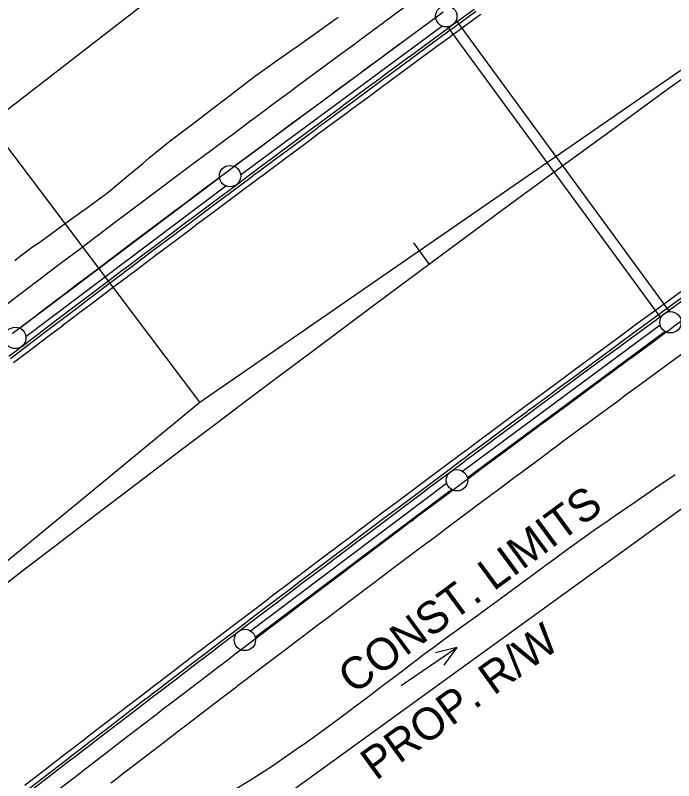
# Model space of a CAD drawing. Extents: x 1147550 to 1149124, y 2017436 to 2018779.
# Drawn here: x 1147976.6 to 1148099.8, y 2017760.9 to 2017904.1 of the extents above; entities that cross this region are included whole.
import ezdxf

# ---------------------------------------------------------------- set-up
doc = ezdxf.new("R2010")
doc.units = 0
for name, color, linetype in [('S_EDGE_CONCRETE', 7, 'Continuous'), ('S_MAILBOX', 7, 'Continuous'), ('S_RDW_PT_SYM', 7, 'Continuous'), ('S_SECONDARY_CTL', 7, 'Continuous'), ('S_TANK', 7, 'Continuous'), ('S_TELEPHONE_UTILITIES', 7, 'Continuous'), ('S_TELEPHONE_UTILITIES_ANNOT', 7, 'Continuous')]:
    doc.layers.add(name, color=color, linetype=linetype)

msp = doc.modelspace()

# ---------------------------------------------------------------- linework, layer by layer
at = {"layer": 'S_EDGE_CONCRETE'}
for p, q in [((1148011.14, 2017831.73), (1148208.89, 2017968.31)), ((1147825.51, 2017679.08), (1148011.14, 2017831.73))]:
    msp.add_line(p, q, dxfattribs=at)
msp.add_lwpolyline([(1148051.07, 2017861.54), (1148054.05, 2017857.52)], dxfattribs=at)
msp.add_arc((1151464.82, 2013253.76), 5729.58, 124.62946, 129.43332, dxfattribs=at)
at = {"layer": 'S_MAILBOX'}
for points in [[(1147550.1, 2017525.89), (1147894.72, 2017801.4), (1147903.55, 2017831.14), (1148035.64, 2017933.4), (1148261.5, 2018084.85), (1148285.74, 2018084.65), (1148479.1, 2018223.18), (1148835.76, 2018573.62)], [(1147623.68, 2017436.42), (1147751.67, 2017548.43), (1147958.55, 2017704.02), (1148020.45, 2017753.36), (1148124.6, 2017828.73), (1148174.25, 2017853.51), (1148282.74, 2017941.53), (1148421.63, 2018031.39), (1148612.18, 2018197.22), (1148639.91, 2018214.06), (1148753.45, 2018306.48), (1148799.03, 2018350.69)]]:
    msp.add_lwpolyline(points, dxfattribs=at)
at = {"layer": 'S_RDW_PT_SYM'}
msp.add_lwpolyline([(1148011.14, 2017831.73), (1147938.86, 2017927.53)], dxfattribs=at)
at = {"layer": 'S_SECONDARY_CTL'}
for points in [[(1147976.51, 2017858.28), (1147977.59, 2017859.11), (1147979.56, 2017860.62), (1147981.65, 2017862.09), (1147985.74, 2017865.05), (1147988.57, 2017867.1), (1147988.68, 2017867.18), (1147989.82, 2017868.01), (1147992.23, 2017869.76), (1147993.88, 2017870.99), (1147997.77, 2017874.22), (1148000.42, 2017876.43), (1148000.58, 2017876.56), (1148001.64, 2017877.45), (1148004.32, 2017879.68), (1148005.54, 2017880.65), (1148009.58, 2017883.66), (1148012.26, 2017885.71), (1148012.55, 2017885.93), (1148013.59, 2017886.73), (1148016.75, 2017889.15), (1148017.6, 2017889.79), (1148021.6, 2017892.85), (1148024.32, 2017894.82), (1148024.62, 2017895.03), (1148025.7, 2017895.79), (1148029.36, 2017898.37), (1148029.82, 2017898.7), (1148033.94, 2017901.6), (1148036.65, 2017903.51), (1148036.99, 2017903.76)], [(1148017.72, 2017759.31), (1148020.73, 2017761.13), (1148024.9, 2017763.83), (1148027.72, 2017765.8), (1148027.85, 2017765.89), (1148028.96, 2017766.67), (1148030.56, 2017767.78), (1148033.02, 2017769.5), (1148037, 2017772.45), (1148039.72, 2017774.48), (1148039.89, 2017774.61), (1148040.96, 2017775.42), (1148042.9, 2017776.89), (1148044.91, 2017778.4), (1148048.87, 2017781.37), (1148051.6, 2017783.45), (1148051.7, 2017783.54), (1148052.8, 2017784.38), (1148055.16, 2017786.11), (1148056.79, 2017787.31), (1148060.79, 2017790.22), (1148063.54, 2017792.22), (1148063.7, 2017792.33), (1148064.81, 2017793.11), (1148067.56, 2017795.14), (1148068.79, 2017796.05), (1148072.78, 2017798.99), (1148075.44, 2017800.95), (1148075.73, 2017801.16), (1148076.77, 2017801.92), (1148079.92, 2017804.23), (1148080.76, 2017804.84), (1148084.77, 2017807.74), (1148087.49, 2017809.61), (1148087.78, 2017809.81), (1148088.85, 2017810.55), (1148092.48, 2017813.04), (1148092.93, 2017813.35), (1148097.02, 2017816.15), (1148099.71, 2017817.98), (1148100.05, 2017818.23)]]:
    msp.add_lwpolyline(points, dxfattribs=at)
at = {"layer": 'S_TANK'}
for p, q in [((1148048.8, 2017778.76), (1148059.18, 2017785.86)), ((1148059.18, 2017785.86), (1148055.21, 2017784.84)), ((1148059.18, 2017785.86), (1148056.79, 2017782.53))]:
    msp.add_line(p, q, dxfattribs=at)
at = {"layer": 'S_TELEPHONE_UTILITIES'}
for points in [[(1147972.95, 2017848.55), (1147976.96, 2017851.6), (1147979.72, 2017853.69), (1147979.89, 2017853.82), (1147980.97, 2017854.64), (1147982.95, 2017856.14), (1147984.99, 2017857.68), (1147989.01, 2017860.71), (1147991.8, 2017862.82), (1147991.91, 2017862.9), (1147993.03, 2017863.75), (1147995.41, 2017865.54), (1147997.05, 2017866.77), (1148001.08, 2017869.8), (1148003.84, 2017871.87), (1148004, 2017871.99), (1148005.11, 2017872.82), (1148007.9, 2017874.9), (1148009.14, 2017875.84), (1148013.18, 2017878.85), (1148015.87, 2017880.86), (1148016.16, 2017881.08), (1148017.21, 2017881.86), (1148020.41, 2017884.24), (1148021.26, 2017884.87), (1148025.3, 2017887.87), (1148027.99, 2017889.87), (1148028.28, 2017890.08), (1148029.34, 2017890.87), (1148032.94, 2017893.53), (1148033.39, 2017893.87), (1148037.44, 2017896.86), (1148040.1, 2017898.82), (1148040.45, 2017899.07), (1148041.49, 2017899.85), (1148045.5, 2017902.8), (1148045.55, 2017902.83), (1148049.61, 2017905.82)], [(1147975.36, 2017840.34), (1147977.79, 2017842.18), (1147981.79, 2017845.22), (1147984.55, 2017847.31), (1147984.72, 2017847.44), (1147985.8, 2017848.26), (1147987.78, 2017849.76), (1147989.81, 2017851.3), (1147993.83, 2017854.33), (1147996.61, 2017856.43), (1147996.72, 2017856.51), (1147997.84, 2017857.35), (1148000.22, 2017859.14), (1148001.86, 2017860.38), (1148005.88, 2017863.4), (1148008.64, 2017865.47), (1148008.8, 2017865.59), (1148009.91, 2017866.42), (1148012.69, 2017868.5), (1148013.93, 2017869.43), (1148017.96, 2017872.44), (1148020.65, 2017874.45), (1148020.95, 2017874.66), (1148021.99, 2017875.44), (1148025.18, 2017877.82), (1148026.03, 2017878.45), (1148030.07, 2017881.45), (1148032.75, 2017883.44), (1148033.05, 2017883.66), (1148034.11, 2017884.44), (1148037.7, 2017887.1), (1148038.15, 2017887.43), (1148042.19, 2017890.42), (1148044.85, 2017892.38), (1148045.19, 2017892.64), (1148046.24, 2017893.41), (1148050.24, 2017896.35), (1148050.29, 2017896.39), (1148054.34, 2017899.37), (1148056.93, 2017901.27), (1148057.39, 2017901.6), (1148058.4, 2017902.34), (1148062.46, 2017905.31)], [(1147975.66, 2017839.94), (1147978.09, 2017841.79), (1147982.1, 2017844.83), (1147984.85, 2017846.91), (1147985.02, 2017847.04), (1147986.1, 2017847.86), (1147988.08, 2017849.36), (1147990.11, 2017850.9), (1147994.13, 2017853.93), (1147996.91, 2017856.03), (1147997.02, 2017856.11), (1147998.14, 2017856.96), (1148000.52, 2017858.74), (1148002.16, 2017859.98), (1148006.18, 2017863), (1148008.94, 2017865.07), (1148009.1, 2017865.19), (1148010.21, 2017866.02), (1148012.99, 2017868.1), (1148014.23, 2017869.03), (1148018.26, 2017872.04), (1148020.95, 2017874.04), (1148021.24, 2017874.26), (1148022.29, 2017875.04), (1148025.48, 2017877.42), (1148026.33, 2017878.05), (1148030.36, 2017881.04), (1148033.05, 2017883.04), (1148033.34, 2017883.26), (1148034.4, 2017884.04), (1148038, 2017886.7), (1148038.45, 2017887.03), (1148042.49, 2017890.02), (1148045.15, 2017891.98), (1148045.49, 2017892.23), (1148046.54, 2017893.01), (1148050.54, 2017895.95), (1148050.59, 2017895.99), (1148054.64, 2017898.96), (1148057.23, 2017900.86), (1148057.69, 2017901.2), (1148058.69, 2017901.94), (1148062.75, 2017904.91)], [(1147975.97, 2017844.57), (1147979.98, 2017847.61), (1147982.73, 2017849.7), (1147982.91, 2017849.83), (1147983.99, 2017850.65), (1147985.97, 2017852.15), (1147988, 2017853.69), (1147992.02, 2017856.72), (1147994.8, 2017858.82), (1147994.92, 2017858.91), (1147996.04, 2017859.75), (1147998.42, 2017861.54), (1148000.06, 2017862.78), (1148004.08, 2017865.8), (1148006.84, 2017867.87), (1148007, 2017867.99), (1148008.11, 2017868.82), (1148010.89, 2017870.9), (1148012.14, 2017871.83), (1148016.17, 2017874.84), (1148018.86, 2017876.85), (1148019.15, 2017877.07), (1148020.2, 2017877.85), (1148023.39, 2017880.22), (1148024.24, 2017880.85), (1148028.28, 2017883.86), (1148030.97, 2017885.85), (1148031.26, 2017886.07), (1148032.32, 2017886.85), (1148035.92, 2017889.51), (1148036.36, 2017889.85), (1148040.41, 2017892.84), (1148043.07, 2017894.8), (1148043.41, 2017895.05), (1148044.46, 2017895.82), (1148048.47, 2017898.77), (1148048.51, 2017898.81), (1148052.57, 2017901.79), (1148055.16, 2017903.69), (1148055.62, 2017904.02), (1148056.63, 2017904.76)], [(1147976.27, 2017839.14), (1147978.7, 2017840.99), (1147982.7, 2017844.03), (1147985.45, 2017846.12), (1147985.62, 2017846.25), (1147986.71, 2017847.07), (1147988.68, 2017848.56), (1147990.72, 2017850.1), (1147994.73, 2017853.13), (1147997.51, 2017855.23), (1147997.62, 2017855.31), (1147998.74, 2017856.16), (1148001.12, 2017857.94), (1148002.76, 2017859.18), (1148006.78, 2017862.2), (1148009.54, 2017864.27), (1148009.7, 2017864.39), (1148010.81, 2017865.21), (1148013.59, 2017867.3), (1148014.83, 2017868.23), (1148018.86, 2017871.24), (1148021.55, 2017873.24), (1148021.84, 2017873.46), (1148022.89, 2017874.24), (1148026.08, 2017876.61), (1148026.92, 2017877.24), (1148030.96, 2017880.24), (1148033.65, 2017882.24), (1148033.94, 2017882.45), (1148035, 2017883.24), (1148038.59, 2017885.9), (1148039.04, 2017886.23), (1148043.08, 2017889.22), (1148045.74, 2017891.18), (1148046.08, 2017891.43), (1148047.13, 2017892.2), (1148051.13, 2017895.15), (1148051.18, 2017895.18), (1148055.23, 2017898.16), (1148057.82, 2017900.06), (1148058.28, 2017900.39), (1148059.29, 2017901.13), (1148063.34, 2017904.1), (1148063.7, 2017904.36)], [(1147978.34, 2017760.07), (1147981.9, 2017762.82), (1147985.84, 2017765.86), (1147986.62, 2017766.46), (1147988.64, 2017768.02), (1147988.65, 2017768.02), (1147989.77, 2017768.89), (1147990.54, 2017769.48), (1147993.72, 2017771.92), (1147997.66, 2017774.95), (1148000.43, 2017777.07), (1148000.5, 2017777.12), (1148001.61, 2017777.97), (1148002.77, 2017778.86), (1148005.56, 2017780.99), (1148009.51, 2017784.01), (1148012.25, 2017786.1), (1148012.38, 2017786.2), (1148013.46, 2017787.02), (1148015.02, 2017788.21), (1148017.42, 2017790.03), (1148021.38, 2017793.04), (1148024.1, 2017795.1), (1148024.27, 2017795.23), (1148025.34, 2017796.04), (1148027.29, 2017797.52), (1148029.31, 2017799.04), (1148033.28, 2017802.04), (1148036.03, 2017804.11), (1148036.14, 2017804.2), (1148037.25, 2017805.03), (1148039.6, 2017806.8), (1148041.22, 2017808.02), (1148045.19, 2017811.01), (1148047.92, 2017813.05), (1148048.08, 2017813.17), (1148049.17, 2017813.99), (1148051.92, 2017816.05), (1148053.15, 2017816.97), (1148057.14, 2017819.95), (1148059.8, 2017821.93), (1148060.09, 2017822.14), (1148061.12, 2017822.92), (1148064.27, 2017825.26), (1148065.11, 2017825.89), (1148069.1, 2017828.85), (1148071.76, 2017830.82), (1148072.05, 2017831.04), (1148073.1, 2017831.81), (1148076.65, 2017834.44), (1148077.09, 2017834.77), (1148081.09, 2017837.72), (1148083.72, 2017839.66), (1148084.06, 2017839.91), (1148085.09, 2017840.68), (1148089.05, 2017843.59), (1148089.1, 2017843.62), (1148093.1, 2017846.57), (1148095.67, 2017848.45), (1148096.12, 2017848.78), (1148097.11, 2017849.51), (1148101.13, 2017852.45)], [(1147978.95, 2017759.28), (1147982.51, 2017762.03), (1147986.45, 2017765.06), (1147987.23, 2017765.67), (1147989.25, 2017767.22), (1147989.26, 2017767.23), (1147990.38, 2017768.1), (1147991.15, 2017768.69), (1147994.32, 2017771.13), (1147998.27, 2017774.16), (1148001.04, 2017776.28), (1148001.11, 2017776.33), (1148002.21, 2017777.18), (1148003.37, 2017778.07), (1148006.16, 2017780.2), (1148010.11, 2017783.22), (1148012.86, 2017785.31), (1148012.98, 2017785.4), (1148014.07, 2017786.23), (1148015.62, 2017787.41), (1148018.03, 2017789.24), (1148021.98, 2017792.24), (1148024.71, 2017794.31), (1148024.88, 2017794.44), (1148025.95, 2017795.25), (1148027.9, 2017796.72), (1148029.91, 2017798.25), (1148033.88, 2017801.24), (1148036.63, 2017803.32), (1148036.74, 2017803.4), (1148037.85, 2017804.23), (1148040.2, 2017806), (1148041.82, 2017807.22), (1148045.8, 2017810.21), (1148048.52, 2017812.25), (1148048.68, 2017812.37), (1148049.77, 2017813.19), (1148052.52, 2017815.25), (1148053.75, 2017816.17), (1148057.74, 2017819.14), (1148060.39, 2017821.13), (1148060.68, 2017821.34), (1148061.72, 2017822.12), (1148064.87, 2017824.46), (1148065.71, 2017825.08), (1148069.7, 2017828.05), (1148072.36, 2017830.02), (1148072.64, 2017830.23), (1148073.69, 2017831.01), (1148077.25, 2017833.64), (1148077.69, 2017833.97), (1148081.69, 2017836.92), (1148084.31, 2017838.86), (1148084.65, 2017839.11), (1148085.69, 2017839.87), (1148089.64, 2017842.78), (1148089.69, 2017842.82), (1148093.7, 2017845.76), (1148096.26, 2017847.64), (1148096.71, 2017847.97), (1148097.71, 2017848.7), (1148101.72, 2017851.64)], [(1147979.26, 2017758.88), (1147982.82, 2017761.63), (1147986.75, 2017764.67), (1147987.54, 2017765.28), (1147989.55, 2017766.83), (1147989.56, 2017766.83), (1147990.69, 2017767.7), (1147991.45, 2017768.29), (1147994.63, 2017770.73), (1147998.57, 2017773.76), (1148001.35, 2017775.88), (1148001.41, 2017775.93), (1148002.52, 2017776.78), (1148003.68, 2017777.67), (1148006.47, 2017779.8), (1148010.42, 2017782.82), (1148013.16, 2017784.91), (1148013.29, 2017785), (1148014.37, 2017785.83), (1148015.93, 2017787.01), (1148018.33, 2017788.84), (1148022.29, 2017791.85), (1148025.01, 2017793.91), (1148025.18, 2017794.04), (1148026.25, 2017794.85), (1148028.2, 2017796.32), (1148030.21, 2017797.85), (1148034.18, 2017800.84), (1148036.93, 2017802.92), (1148037.04, 2017803), (1148038.15, 2017803.83), (1148040.5, 2017805.6), (1148042.12, 2017806.82), (1148046.1, 2017809.81), (1148048.82, 2017811.85), (1148048.98, 2017811.97), (1148050.07, 2017812.79), (1148052.82, 2017814.85), (1148054.05, 2017815.77), (1148058.03, 2017818.74), (1148060.69, 2017820.73), (1148060.98, 2017820.94), (1148062.02, 2017821.71), (1148065.17, 2017824.06), (1148066.01, 2017824.68), (1148070, 2017827.65), (1148072.65, 2017829.62), (1148072.94, 2017829.83), (1148073.99, 2017830.61), (1148077.54, 2017833.24), (1148077.99, 2017833.56), (1148081.98, 2017836.52), (1148084.61, 2017838.46), (1148084.95, 2017838.71), (1148085.98, 2017839.47), (1148089.94, 2017842.38), (1148089.99, 2017842.42), (1148093.99, 2017845.36), (1148096.55, 2017847.24), (1148097.01, 2017847.57), (1148098, 2017848.3), (1148102.01, 2017851.23)], [(1147984.65, 2017759.26), (1147988.58, 2017762.29), (1147989.37, 2017762.9), (1147991.38, 2017764.45), (1147991.39, 2017764.46), (1147992.52, 2017765.32), (1147993.28, 2017765.91), (1147996.46, 2017768.35), (1148000.4, 2017771.38), (1148003.17, 2017773.5), (1148003.23, 2017773.55), (1148004.34, 2017774.4), (1148005.5, 2017775.29), (1148008.29, 2017777.42), (1148012.24, 2017780.43), (1148014.98, 2017782.52), (1148015.1, 2017782.62), (1148016.19, 2017783.44), (1148017.74, 2017784.63), (1148020.14, 2017786.45), (1148024.1, 2017789.46), (1148026.82, 2017791.52), (1148026.99, 2017791.65), (1148028.06, 2017792.46), (1148030.01, 2017793.93), (1148032.02, 2017795.45), (1148035.99, 2017798.45), (1148038.74, 2017800.52), (1148038.85, 2017800.6), (1148039.95, 2017801.44), (1148042.3, 2017803.21), (1148043.92, 2017804.43), (1148047.9, 2017807.41), (1148050.62, 2017809.45), (1148050.78, 2017809.57), (1148051.87, 2017810.39), (1148054.62, 2017812.45), (1148055.85, 2017813.37), (1148059.83, 2017816.34), (1148062.49, 2017818.32), (1148062.78, 2017818.54), (1148063.81, 2017819.31), (1148066.96, 2017821.65), (1148067.8, 2017822.27), (1148071.79, 2017825.24), (1148074.44, 2017827.21), (1148074.73, 2017827.42), (1148075.78, 2017828.2), (1148079.33, 2017830.82), (1148079.77, 2017831.15), (1148083.76, 2017834.1), (1148086.39, 2017836.04), (1148086.73, 2017836.29), (1148087.76, 2017837.05), (1148091.72, 2017839.96), (1148091.76, 2017840), (1148095.77, 2017842.94), (1148098.33, 2017844.82), (1148098.78, 2017845.15), (1148099.77, 2017845.88), (1148103.78, 2017848.81)], [(1147994.44, 2017760.49), (1147995.57, 2017761.36), (1147996.33, 2017761.95), (1147999.5, 2017764.39), (1148003.44, 2017767.41), (1148006.21, 2017769.53), (1148006.27, 2017769.58), (1148007.38, 2017770.43), (1148008.54, 2017771.31), (1148011.32, 2017773.44), (1148015.27, 2017776.46), (1148018.01, 2017778.54), (1148018.13, 2017778.64), (1148019.22, 2017779.47), (1148020.77, 2017780.65), (1148023.17, 2017782.47), (1148027.12, 2017785.47), (1148029.84, 2017787.53), (1148030.01, 2017787.66), (1148031.08, 2017788.47), (1148033.03, 2017789.94), (1148035.04, 2017791.46), (1148039, 2017794.46), (1148041.74, 2017796.53), (1148041.85, 2017796.61), (1148042.96, 2017797.44), (1148045.31, 2017799.21), (1148046.93, 2017800.43), (1148050.9, 2017803.41), (1148053.62, 2017805.45), (1148053.78, 2017805.57), (1148054.87, 2017806.39), (1148057.61, 2017808.44), (1148058.84, 2017809.36), (1148062.82, 2017812.33), (1148065.47, 2017814.31), (1148065.76, 2017814.53), (1148066.8, 2017815.3), (1148069.94, 2017817.64), (1148070.78, 2017818.26), (1148074.77, 2017821.22), (1148077.42, 2017823.19), (1148077.71, 2017823.4), (1148078.75, 2017824.18), (1148082.3, 2017826.81), (1148082.74, 2017827.13), (1148086.73, 2017830.08), (1148089.36, 2017832.02), (1148089.7, 2017832.27), (1148090.73, 2017833.03), (1148094.68, 2017835.94), (1148094.73, 2017835.97), (1148098.73, 2017838.91), (1148101.28, 2017840.79)]]:
    msp.add_lwpolyline(points, dxfattribs=at)
at = {"layer": 'S_TELEPHONE_UTILITIES_ANNOT'}
for p, q in [((1148017.56, 2017875.88), (1148055.23, 2017903.73)), ((1148017.56, 2017875.88), (1148055.23, 2017903.73)), ((1148059.05, 2017903.15), (1148098.97, 2017848.67)), ((1148059.05, 2017903.15), (1148098.97, 2017848.67)), ((1148018.75, 2017874.27), (1148056.42, 2017902.12)), ((1148018.75, 2017874.27), (1148056.42, 2017902.12)), ((1148057.43, 2017901.97), (1148097.35, 2017847.49)), ((1148057.43, 2017901.97), (1148097.35, 2017847.49)), ((1147977.36, 2017845.62), (1148014.78, 2017873.8)), ((1147977.36, 2017845.62), (1148014.78, 2017873.8)), ((1147978.56, 2017844.02), (1148015.98, 2017872.2)), ((1147978.56, 2017844.02), (1148015.98, 2017872.2)), ((1148060.28, 2017818.85), (1148097.25, 2017846.19)), ((1148060.28, 2017818.85), (1148097.25, 2017846.19)), ((1148061.17, 2017817.64), (1148098.14, 2017844.98)), ((1148061.17, 2017817.64), (1148098.14, 2017844.98)), ((1148020.57, 2017788.96), (1148057.3, 2017816.62)), ((1148020.57, 2017788.96), (1148057.3, 2017816.62)), ((1148021.47, 2017787.76), (1148058.2, 2017815.43)), ((1148021.47, 2017787.76), (1148058.2, 2017815.43))]:
    msp.add_line(p, q, dxfattribs=at)
for centre in [(1148057.22, 2017903.95), (1148016.77, 2017874.04), (1148099.18, 2017846.69), (1147976.58, 2017843.78), (1148059.23, 2017817.14), (1148019.54, 2017787.25)]:
    msp.add_circle(centre, 2, dxfattribs=at)

# ---------------------------------------------------------------- texts
at = {"layer": 'S_MAILBOX'}
msp.add_text('PROP. R/W', height=6, rotation=35.8922, dxfattribs=at).set_placement((1148044.07, 2017760.82))
at = {"layer": 'S_SECONDARY_CTL'}
msp.add_text('CONST. LIMITS', height=6, rotation=36.4341, dxfattribs=at).set_placement((1148039.9, 2017776.96))

doc.saveas('drawing.dxf')
